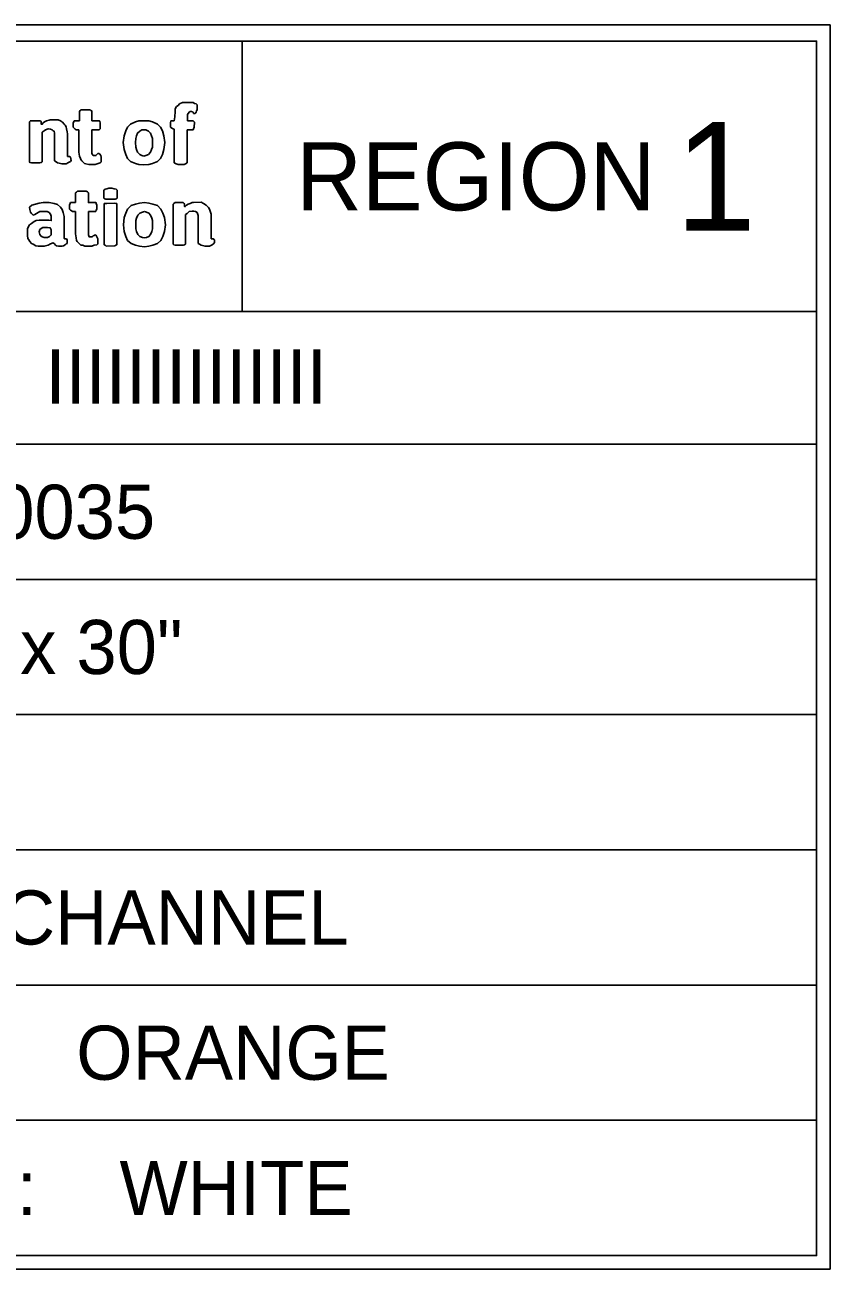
# Model space of a CAD drawing. Extents: x 1775472.9 to 1775494.7, y 1032415.7 to 1032420.8.
# Drawn here: x 1775492.959 to 1775494.717, y 1032418.059 to 1032420.776 of the extents above; entities that cross this region are included whole.
import ezdxf

# ---------------------------------------------------------------- set-up
doc = ezdxf.new("R2010")
doc.units = 0
doc.layers.add('GSSHT', color=7, linetype='Continuous')
doc.layers.add('O_GS_Sht', color=7, linetype='Continuous')

msp = doc.modelspace()

# ---------------------------------------------------------------- linework, layer by layer
at = {"layer": 'GSSHT'}
for p, q in [((1775490.8483, 1032420.1501), (1775494.6872, 1032420.1501)), ((1775490.8483, 1032419.8607), (1775494.6872, 1032419.8607)), ((1775490.8483, 1032419.5654), (1775494.6872, 1032419.5654)), ((1775490.8483, 1032419.2701), (1775494.6872, 1032419.2701)), ((1775490.8483, 1032418.9748), (1775494.6872, 1032418.9748)), ((1775490.8483, 1032418.6795), (1775494.6872, 1032418.6795)), ((1775490.8483, 1032418.3842), (1775494.6872, 1032418.3842))]:
    msp.add_line(p, q, dxfattribs=at)
for points in [[(1775490.8187, 1032420.7761), (1775494.7168, 1032420.7761), (1775494.7168, 1032418.0593), (1775490.8187, 1032418.0593)], [(1775490.8483, 1032420.7407), (1775494.6872, 1032420.7407), (1775494.6872, 1032418.0889), (1775490.8483, 1032418.0889)]]:
    msp.add_lwpolyline(points, close=True, dxfattribs=at)
msp.add_lwpolyline([(1775493.4332, 1032420.1501), (1775493.4332, 1032420.7407)], dxfattribs=at)
at = {"layer": 'O_GS_Sht'}
for p, q in [((1775493.0781, 1032420.5873), (1775493.0781, 1032420.5667)), ((1775493.2874, 1032420.5873), (1775493.2861, 1032420.5754)), ((1775493.2904, 1032420.5982), (1775493.2874, 1032420.5928)), ((1775493.2874, 1032420.5928), (1775493.2874, 1032420.5873)), ((1775493.2939, 1032420.6003), (1775493.2904, 1032420.5982)), ((1775493.2969, 1032420.6036), (1775493.2939, 1032420.6003)), ((1775493.3034, 1032420.6068), (1775493.2969, 1032420.6036)), ((1775493.3143, 1032420.6068), (1775493.3034, 1032420.6068)), ((1775493.3264, 1032420.6068), (1775493.3143, 1032420.6068)), ((1775493.3143, 1032420.5808), (1775493.3156, 1032420.583)), ((1775493.3156, 1032420.583), (1775493.3186, 1032420.5862)), ((1775493.3186, 1032420.5862), (1775493.3199, 1032420.5873)), ((1775493.3199, 1032420.5873), (1775493.3229, 1032420.5873)), ((1775493.3229, 1032420.5873), (1775493.3264, 1032420.5852)), ((1775493.3294, 1032420.6047), (1775493.3264, 1032420.6068)), ((1775493.3264, 1032420.5852), (1775493.3273, 1032420.583)), ((1775493.3273, 1032420.583), (1775493.3307, 1032420.583)), ((1775493.3329, 1032420.6036), (1775493.3294, 1032420.6047)), ((1775493.3307, 1032420.583), (1775493.3329, 1032420.5852)), ((1775493.3351, 1032420.6014), (1775493.3329, 1032420.6036)), ((1775493.3329, 1032420.5852), (1775493.3338, 1032420.5884)), ((1775493.3338, 1032420.5884), (1775493.3351, 1032420.5906)), ((1775493.3351, 1032420.5906), (1775493.3351, 1032420.6014)), ((1775492.9688, 1032420.5646), (1775492.9688, 1032420.4768)), ((1775493.0781, 1032420.5667), (1775493.0664, 1032420.5667)), ((1775493.2774, 1032420.5667), (1775493.2766, 1032420.5624)), ((1775493.2766, 1032420.5624), (1775493.2766, 1032420.5527)), ((1775493.2852, 1032420.5667), (1775493.2774, 1032420.5667)), ((1775493.2861, 1032420.5754), (1775493.2852, 1032420.5667)), ((1775493.3143, 1032420.5667), (1775493.3143, 1032420.5808)), ((1775493.3264, 1032420.5667), (1775493.3143, 1032420.5667)), ((1775493.3273, 1032420.5657), (1775493.3264, 1032420.5667)), ((1775493.3294, 1032420.5635), (1775493.3273, 1032420.5657)), ((1775493.3286, 1032420.5527), (1775493.3294, 1032420.5635)), ((1775492.997, 1032420.4768), (1775492.997, 1032420.5418)), ((1775493.0239, 1032420.5397), (1775493.0239, 1032420.479)), ((1775493.0521, 1032420.5386), (1775493.0512, 1032420.5429)), ((1775493.0521, 1032420.4887), (1775493.0521, 1032420.5386)), ((1775493.0707, 1032420.5472), (1775493.0772, 1032420.5472)), ((1775493.0772, 1032420.5472), (1775493.0772, 1032420.4985)), ((1775493.1054, 1032420.4963), (1775493.1054, 1032420.5472)), ((1775493.1054, 1032420.5472), (1775493.1214, 1032420.5472)), ((1775493.2766, 1032420.5527), (1775493.2796, 1032420.5505)), ((1775493.2796, 1032420.5505), (1775493.2831, 1032420.5494)), ((1775493.2831, 1032420.5494), (1775493.2852, 1032420.5483)), ((1775493.2852, 1032420.5483), (1775493.2852, 1032420.4746)), ((1775493.3134, 1032420.4746), (1775493.3134, 1032420.5472)), ((1775493.3134, 1032420.5472), (1775493.3264, 1032420.5472)), ((1775493.3264, 1032420.5472), (1775493.3273, 1032420.5494)), ((1775493.3273, 1032420.5494), (1775493.3286, 1032420.5527)), ((1775493.2852, 1032420.4746), (1775493.2896, 1032420.4725)), ((1775493.3099, 1032420.4725), (1775493.3134, 1032420.4746)), ((1775493.2189, 1032420.4703), (1775493.2298, 1032420.4714)), ((1775493.2896, 1032420.4725), (1775493.2939, 1032420.4714)), ((1775493.2939, 1032420.4714), (1775493.3069, 1032420.4714)), ((1775493.3069, 1032420.4714), (1775493.3099, 1032420.4725)), ((1775493.1422, 1032420.4194), (1775493.1379, 1032420.4183)), ((1775493.1487, 1032420.4194), (1775493.1422, 1032420.4194)), ((1775493.1539, 1032420.4183), (1775493.1487, 1032420.4194)), ((1775493.0694, 1032420.4096), (1775493.0694, 1032420.388)), ((1775493.1344, 1032420.4172), (1775493.1314, 1032420.4151)), ((1775493.1314, 1032420.4151), (1775493.1314, 1032420.3977)), ((1775493.1314, 1032420.3977), (1775493.1335, 1032420.3966)), ((1775493.1335, 1032420.3966), (1775493.1357, 1032420.3956)), ((1775493.1379, 1032420.4183), (1775493.1344, 1032420.4172)), ((1775493.1357, 1032420.3956), (1775493.1561, 1032420.3956)), ((1775493.1582, 1032420.4172), (1775493.1539, 1032420.4183)), ((1775493.1561, 1032420.3956), (1775493.1582, 1032420.3966)), ((1775493.1604, 1032420.4151), (1775493.1582, 1032420.4172)), ((1775493.1582, 1032420.3966), (1775493.1604, 1032420.3977)), ((1775493.1604, 1032420.3977), (1775493.1604, 1032420.4151)), ((1775493.0694, 1032420.388), (1775493.0586, 1032420.388)), ((1775493.0629, 1032420.3685), (1775493.0694, 1032420.3685)), ((1775493.0694, 1032420.3685), (1775493.0694, 1032420.3197)), ((1775493.0976, 1032420.3175), (1775493.0976, 1032420.3685)), ((1775493.0976, 1032420.3685), (1775493.114, 1032420.3685)), ((1775493.1344, 1032420.3858), (1775493.1322, 1032420.3858)), ((1775493.1322, 1032420.3858), (1775493.1322, 1032420.2959)), ((1775493.1379, 1032420.3858), (1775493.1344, 1032420.3858)), ((1775493.1539, 1032420.3869), (1775493.1379, 1032420.3858)), ((1775493.1574, 1032420.3858), (1775493.1539, 1032420.3869)), ((1775493.1595, 1032420.3858), (1775493.1574, 1032420.3858)), ((1775493.1595, 1032420.2959), (1775493.1595, 1032420.3858)), ((1775493.2831, 1032420.3847), (1775493.2831, 1032420.297)), ((1775493.3099, 1032420.297), (1775493.3099, 1032420.362)), ((1775493.3372, 1032420.3598), (1775493.3372, 1032420.2991)), ((1775493.3654, 1032420.3598), (1775493.3654, 1032420.363)), ((1775493.3654, 1032420.3089), (1775493.3654, 1032420.3598)), ((1775493.1322, 1032420.2959), (1775493.1344, 1032420.2948)), ((1775493.1344, 1032420.2948), (1775493.1366, 1032420.2926)), ((1775493.1366, 1032420.2926), (1775493.1552, 1032420.2937)), ((1775493.1552, 1032420.2937), (1775493.1574, 1032420.2948)), ((1775493.1574, 1032420.2948), (1775493.1595, 1032420.2959)), ((1775493.2202, 1032420.2915), (1775493.2298, 1032420.2926))]:
    msp.add_line(p, q, dxfattribs=at)
for points in [[(1775493.0815, 1032420.5906), (1775493.0794, 1032420.5895), (1775493.0781, 1032420.5873)], [(1775493.1054, 1032420.5884), (1775493.1032, 1032420.5895), (1775493.1019, 1032420.5906), (1775493.0815, 1032420.5906)], [(1775493.1236, 1032420.5613), (1775493.1227, 1032420.5657), (1775493.1214, 1032420.5667), (1775493.1054, 1032420.5667), (1775493.1054, 1032420.5884)], [(1775493.0512, 1032420.5429), (1775493.0499, 1032420.5494), (1775493.049, 1032420.5537), (1775493.0469, 1032420.557), (1775493.0447, 1032420.5592), (1775493.0412, 1032420.5635), (1775493.0369, 1032420.5667), (1775493.0317, 1032420.5689), (1775493.0144, 1032420.5689), (1775493.0122, 1032420.5678), (1775493.0066, 1032420.5667), (1775493.0022, 1032420.5646), (1775492.9992, 1032420.5624), (1775492.997, 1032420.5592), (1775492.9949, 1032420.5592), (1775492.9949, 1032420.5646), (1775492.9936, 1032420.5657), (1775492.9914, 1032420.5667), (1775492.9754, 1032420.5667), (1775492.971, 1032420.5667), (1775492.9688, 1032420.5646)], [(1775493.0664, 1032420.5667), (1775493.0642, 1032420.5613), (1775493.0642, 1032420.5527)], [(1775493.1214, 1032420.5472), (1775493.1236, 1032420.5494), (1775493.1236, 1032420.5527), (1775493.1236, 1032420.5613)], [(1775493.2189, 1032420.5667), (1775493.2081, 1032420.5667), (1775493.2007, 1032420.5646), (1775493.1899, 1032420.5592), (1775493.1834, 1032420.5527), (1775493.1791, 1032420.5451), (1775493.1756, 1032420.5342), (1775493.1734, 1032420.5191)], [(1775493.2644, 1032420.5191), (1775493.2623, 1032420.5342), (1775493.2592, 1032420.5451), (1775493.2549, 1032420.5527), (1775493.2484, 1032420.5592), (1775493.2376, 1032420.5646), (1775493.2298, 1032420.5667), (1775493.2189, 1032420.5667)], [(1775492.997, 1032420.5418), (1775493.0014, 1032420.5451), (1775493.0044, 1032420.5472), (1775493.01, 1032420.5494), (1775493.0152, 1032420.5483), (1775493.0187, 1032420.5472), (1775493.0209, 1032420.5451), (1775493.023, 1032420.544), (1775493.0239, 1032420.5397)], [(1775493.0642, 1032420.5527), (1775493.0664, 1032420.5505), (1775493.0685, 1032420.5483), (1775493.0707, 1032420.5472)], [(1775493.2007, 1032420.5191), (1775493.2016, 1032420.5277), (1775493.2029, 1032420.5342), (1775493.2051, 1032420.5397), (1775493.2103, 1032420.544), (1775493.2146, 1032420.5472), (1775493.2189, 1032420.5472)], [(1775493.2189, 1032420.5472), (1775493.2233, 1032420.5472), (1775493.2289, 1032420.544), (1775493.2332, 1032420.5397), (1775493.2354, 1032420.5342), (1775493.2376, 1032420.5277), (1775493.2376, 1032420.5191)], [(1775493.1734, 1032420.5191), (1775493.1756, 1032420.5039), (1775493.1791, 1032420.4931), (1775493.1834, 1032420.4844), (1775493.1899, 1032420.4779), (1775493.2007, 1032420.4736), (1775493.2081, 1032420.4714), (1775493.2189, 1032420.4703)], [(1775493.2189, 1032420.4898), (1775493.2146, 1032420.4909), (1775493.2103, 1032420.4931), (1775493.2051, 1032420.4985), (1775493.2029, 1032420.5039), (1775493.2016, 1032420.5093), (1775493.2007, 1032420.5191)], [(1775493.2376, 1032420.5191), (1775493.2376, 1032420.5093), (1775493.2354, 1032420.5039), (1775493.2332, 1032420.4985), (1775493.2289, 1032420.4931), (1775493.2233, 1032420.4909), (1775493.2189, 1032420.4898)], [(1775493.2298, 1032420.4714), (1775493.2376, 1032420.4736), (1775493.2484, 1032420.4779), (1775493.2549, 1032420.4844), (1775493.2592, 1032420.4931), (1775493.2623, 1032420.5039), (1775493.2644, 1032420.5191)], [(1775492.9688, 1032420.4768), (1775492.9697, 1032420.4757), (1775492.9741, 1032420.4746), (1775492.9914, 1032420.4746), (1775492.9949, 1032420.4757), (1775492.997, 1032420.4768)], [(1775493.0239, 1032420.479), (1775493.0274, 1032420.4768), (1775493.0304, 1032420.4746), (1775493.0404, 1032420.4725), (1775493.049, 1032420.4725), (1775493.0542, 1032420.4757), (1775493.0586, 1032420.4779), (1775493.0599, 1032420.4801), (1775493.0586, 1032420.4876), (1775493.0564, 1032420.4887), (1775493.0521, 1032420.4887)], [(1775493.0772, 1032420.4985), (1775493.0781, 1032420.4898), (1775493.0802, 1032420.4844), (1775493.0815, 1032420.4822), (1775493.0837, 1032420.479), (1775493.0859, 1032420.4768), (1775493.0889, 1032420.4736), (1775493.0924, 1032420.4725), (1775493.0989, 1032420.4714), (1775493.1127, 1032420.4714), (1775493.1192, 1032420.4736), (1775493.1236, 1032420.4746), (1775493.1257, 1032420.4768), (1775493.1257, 1032420.4876)], [(1775493.1257, 1032420.4876), (1775493.1249, 1032420.4909), (1775493.1227, 1032420.4942), (1775493.1205, 1032420.4952), (1775493.1184, 1032420.4952), (1775493.1162, 1032420.4931), (1775493.114, 1032420.4909), (1775493.1084, 1032420.4909), (1775493.1062, 1032420.4942), (1775493.1054, 1032420.4963)], [(1775493.0737, 1032420.4129), (1775493.0716, 1032420.4107), (1775493.0694, 1032420.4096)], [(1775493.0976, 1032420.4096), (1775493.0954, 1032420.4118), (1775493.0932, 1032420.4129), (1775493.0737, 1032420.4129)], [(1775493.1162, 1032420.3825), (1775493.1149, 1032420.3858), (1775493.114, 1032420.388), (1775493.0976, 1032420.388), (1775493.0976, 1032420.4096)], [(1775493.0586, 1032420.388), (1775493.0564, 1032420.3825), (1775493.0564, 1032420.3739)], [(1775493.0564, 1032420.3739), (1775493.0586, 1032420.3717), (1775493.0599, 1032420.3706), (1775493.0629, 1032420.3685)], [(1775493.114, 1032420.3685), (1775493.1149, 1032420.3717), (1775493.1162, 1032420.3739), (1775493.1162, 1032420.3825)], [(1775493.2202, 1032420.388), (1775493.2094, 1032420.3869), (1775493.2007, 1032420.3847), (1775493.1908, 1032420.3815), (1775493.1834, 1032420.3739), (1775493.1791, 1032420.3652), (1775493.1756, 1032420.3555), (1775493.1747, 1032420.3392)], [(1775493.2016, 1032420.3392), (1775493.2016, 1032420.349), (1775493.2029, 1032420.3544), (1775493.2059, 1032420.3609), (1775493.2103, 1032420.3652), (1775493.2159, 1032420.3674), (1775493.2202, 1032420.3685)], [(1775493.2657, 1032420.3392), (1775493.2636, 1032420.3555), (1775493.2601, 1032420.3652), (1775493.2558, 1032420.3739), (1775493.2484, 1032420.3815), (1775493.2384, 1032420.3847), (1775493.2298, 1032420.3869), (1775493.2202, 1032420.388)], [(1775493.2202, 1032420.3685), (1775493.2246, 1032420.3674), (1775493.2298, 1032420.3652), (1775493.2332, 1032420.3609), (1775493.2363, 1032420.3544), (1775493.2376, 1032420.349), (1775493.2376, 1032420.3392)], [(1775493.3654, 1032420.363), (1775493.3632, 1032420.3695), (1775493.3619, 1032420.3739), (1775493.3598, 1032420.3771), (1775493.3576, 1032420.3793), (1775493.3546, 1032420.3825), (1775493.3489, 1032420.3858), (1775493.3437, 1032420.389), (1775493.3273, 1032420.388), (1775493.3242, 1032420.388), (1775493.3199, 1032420.3858), (1775493.3156, 1032420.3847), (1775493.3121, 1032420.3825), (1775493.3091, 1032420.3793), (1775493.3078, 1032420.3793), (1775493.3078, 1032420.3847), (1775493.3069, 1032420.3858), (1775493.3047, 1032420.388), (1775493.2874, 1032420.388), (1775493.2839, 1032420.3858), (1775493.2831, 1032420.3847)], [(1775493.3099, 1032420.362), (1775493.3134, 1032420.3641), (1775493.3177, 1032420.3685), (1775493.3242, 1032420.3695), (1775493.3273, 1032420.3695), (1775493.3316, 1032420.3685), (1775493.3351, 1032420.3663), (1775493.3359, 1032420.3641), (1775493.3372, 1032420.3598)], [(1775493.1747, 1032420.3392), (1775493.1756, 1032420.3251), (1775493.1791, 1032420.3143), (1775493.1834, 1032420.3056), (1775493.1908, 1032420.2991), (1775493.2007, 1032420.2948), (1775493.2094, 1032420.2926), (1775493.2202, 1032420.2915)], [(1775493.2202, 1032420.311), (1775493.2159, 1032420.3121), (1775493.2103, 1032420.3143), (1775493.2059, 1032420.3186), (1775493.2029, 1032420.3251), (1775493.2016, 1032420.3305), (1775493.2016, 1032420.3392)], [(1775493.2376, 1032420.3392), (1775493.2376, 1032420.3305), (1775493.2363, 1032420.3251), (1775493.2332, 1032420.3186), (1775493.2298, 1032420.3143), (1775493.2246, 1032420.3121), (1775493.2202, 1032420.311)], [(1775493.2298, 1032420.2926), (1775493.2384, 1032420.2948), (1775493.2484, 1032420.2991), (1775493.2558, 1032420.3056), (1775493.2601, 1032420.3143), (1775493.2636, 1032420.3251), (1775493.2657, 1032420.3392)], [(1775493.0694, 1032420.3197), (1775493.0707, 1032420.311), (1775493.0716, 1032420.3056), (1775493.0729, 1032420.3035), (1775493.0759, 1032420.3002), (1775493.0781, 1032420.298), (1775493.0815, 1032420.2948), (1775493.0859, 1032420.2948), (1775493.0902, 1032420.2926), (1775493.1054, 1032420.2926), (1775493.1106, 1032420.2948), (1775493.1162, 1032420.2959), (1775493.1184, 1032420.298), (1775493.1184, 1032420.3089)], [(1775493.1184, 1032420.3089), (1775493.1171, 1032420.3121), (1775493.1149, 1032420.3165), (1775493.1127, 1032420.3175), (1775493.1106, 1032420.3165), (1775493.1084, 1032420.3154), (1775493.1062, 1032420.3132), (1775493.0997, 1032420.3132), (1775493.0989, 1032420.3154), (1775493.0976, 1032420.3175)], [(1775493.2831, 1032420.297), (1775493.2839, 1032420.2959), (1775493.2874, 1032420.2948), (1775493.3047, 1032420.2948), (1775493.3078, 1032420.2959), (1775493.3099, 1032420.297)], [(1775493.3372, 1032420.2991), (1775493.3403, 1032420.297), (1775493.3437, 1032420.2948), (1775493.3524, 1032420.2926), (1775493.3619, 1032420.2926), (1775493.3676, 1032420.2959), (1775493.3706, 1032420.298), (1775493.3728, 1032420.3013), (1775493.3728, 1032420.3067), (1775493.3698, 1032420.3089), (1775493.3654, 1032420.3089)]]:
    msp.add_lwpolyline(points, dxfattribs=at)
for points in [[(1775492.9688, 1032420.3782), (1775492.9741, 1032420.3825), (1775492.9819, 1032420.3847), (1775492.9905, 1032420.3869), (1775492.9992, 1032420.388), (1775493.0122, 1032420.388), (1775493.023, 1032420.3858), (1775493.0304, 1032420.3836), (1775493.0369, 1032420.3782), (1775493.0404, 1032420.3728), (1775493.0425, 1032420.3663), (1775493.0447, 1032420.3576), (1775493.0447, 1032420.31), (1775493.0456, 1032420.3089), (1775493.0499, 1032420.3089), (1775493.0512, 1032420.3067), (1775493.0512, 1032420.2991), (1775493.049, 1032420.298), (1775493.0469, 1032420.2959), (1775493.0434, 1032420.2937), (1775493.0404, 1032420.2926), (1775493.0326, 1032420.2926), (1775493.0282, 1032420.2937), (1775493.0261, 1032420.2948), (1775493.0239, 1032420.298), (1775493.0209, 1032420.3002), (1775493.0152, 1032420.298), (1775493.01, 1032420.2948), (1775493.0044, 1032420.2937), (1775493.0014, 1032420.2926), (1775492.9884, 1032420.2926), (1775492.9827, 1032420.2937), (1775492.9775, 1032420.297), (1775492.9732, 1032420.2991), (1775492.9697, 1032420.3035), (1775492.9675, 1032420.3067), (1775492.9654, 1032420.31), (1775492.9645, 1032420.3165), (1775492.9645, 1032420.3305), (1775492.9667, 1032420.336), (1775492.9688, 1032420.3392), (1775492.9732, 1032420.3425), (1775492.9762, 1032420.3446), (1775492.9797, 1032420.3468), (1775492.984, 1032420.349), (1775492.9905, 1032420.35), (1775493.0109, 1032420.35), (1775493.0165, 1032420.349), (1775493.0165, 1032420.3587), (1775493.0152, 1032420.363), (1775493.0122, 1032420.3663), (1775493.0079, 1032420.3685), (1775492.997, 1032420.3685), (1775492.9914, 1032420.3685), (1775492.9884, 1032420.3663), (1775492.9806, 1032420.362), (1775492.9775, 1032420.3609), (1775492.9732, 1032420.3641), (1775492.971, 1032420.3674), (1775492.9697, 1032420.3728)], [(1775492.9914, 1032420.3295), (1775492.9949, 1032420.3316), (1775492.9979, 1032420.3338), (1775493.0035, 1032420.3338), (1775493.0079, 1032420.3338), (1775493.0144, 1032420.3327), (1775493.0165, 1032420.3284), (1775493.0165, 1032420.3175), (1775493.0131, 1032420.3143), (1775493.0087, 1032420.3121), (1775493.0014, 1032420.3121), (1775492.997, 1032420.3132), (1775492.9936, 1032420.3154), (1775492.9914, 1032420.3186), (1775492.9905, 1032420.324)]]:
    msp.add_lwpolyline(points, close=True, dxfattribs=at)

# ---------------------------------------------------------------- texts
at = {"layer": 'GSSHT'}
for s, height, p in [('IIIIIIIIIIIIII', 0.118122, (1775493.004, 1032419.9493)), ('HB-0035', 0.11812, (1775492.6201, 1032419.654)), ('30" x 30"', 0.11812, (1775492.6731, 1032419.3587)), ('STEEL U-CHANNEL', 0.118122, (1775492.2001, 1032418.7681)), ('ORANGE', 0.11812, (1775493.0713, 1032418.4728)), ('LEGEND/BORDER COLOR:', 0.118122, (1775490.9664, 1032418.1774)), ('WHITE', 0.11812, (1775493.1656, 1032418.1774))]:
    msp.add_text(s, height=height, dxfattribs=at).set_placement(p)
at = {"layer": 'O_GS_Sht'}
for s, height, p in [('1', 0.2378, (1775494.3785, 1032420.3265)), ('REGION', 0.14862, (1775493.5513, 1032420.3711))]:
    msp.add_text(s, height=height, dxfattribs=at).set_placement(p)

doc.saveas('drawing.dxf')
